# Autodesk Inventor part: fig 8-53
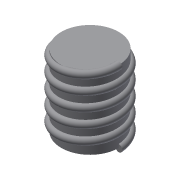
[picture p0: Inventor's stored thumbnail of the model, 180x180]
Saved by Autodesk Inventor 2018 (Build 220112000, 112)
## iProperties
Shininess: 77.0
Length Units: 11269
Angle Units: 11279
Time Units: 11290
Mass Units: 11283
Length Display Precision: 3
Angle Display Precision: 2
Created: 2002-01
Part Number: fig 8-53
Document SubType Name: Modeling
Designer: CADSoft
Density: 1 g/cm^3
Material: Generic
Appearance: Default
Density: 0.0
Volumn: 0.0
Area: 0.0
PropertySet Name: Model Information
Control State: 0
Master: False
Checked Out: False
Author: CADSoft
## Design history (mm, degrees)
sketch "Sketch4"
  geometry: C1 r 20 at (0, 0)
  constraints: 1 centre point
  dimensions: "d44" = 40 diameter of C1
sketch "Sketch2"
  geometry: C1 r 2.5 at (-20, -0.092); 1 further point
  constraints: 1 centre point, 1 other
  dimensions: "d0" = 5 diameter of C1; "d43" = 20 horizontal distance of C1.centre point (0, 0)
extrude "Extrusion2" join sketch "Sketch4" distance "d45" = 50; taper "d46" = 0 deg
coil "Coil6" pitch "d47" = 10; turns "d49" = 5; dims "d48" = 10, "d50" = 0, angle "d51" = 90 deg, angle "d52" = 90 deg, "d53" = 0, "d54" = 0
body "Solid1"
